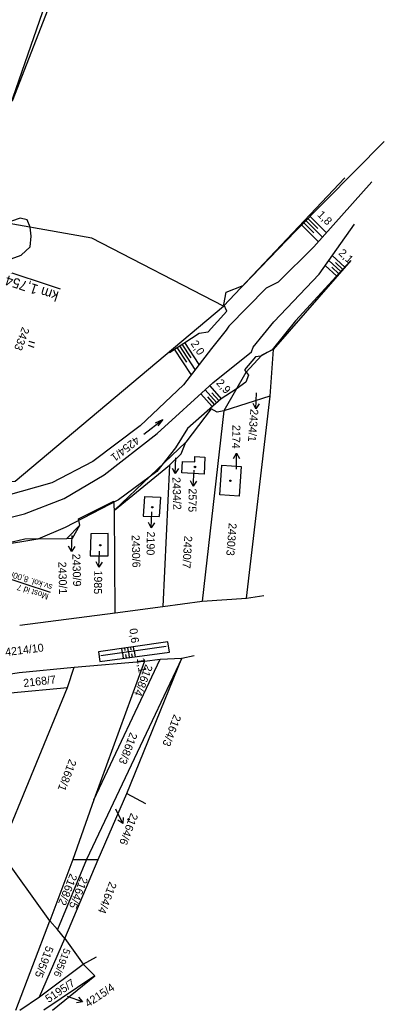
# Model space of a CAD drawing. Extents: x -659211 to -658900, y -1170600 to -1169973.
# Drawn here: x -659028.5 to -658937.4, y -1170600 to -1170352.4 of the extents above; entities that cross this region are included whole.
import ezdxf

# ---------------------------------------------------------------- set-up
doc = ezdxf.new("R2010")
doc.units = 0
for name, color, linetype in [('Vrstva 18', 7, 'Continuous'), ('Vrstva 48', 7, 'Continuous'), ('Vrstva 49', 7, 'Continuous'), ('Vrstva 53', 7, 'Continuous'), ('Vrstva 54', 7, 'Continuous'), ('Vrstva 55', 7, 'Continuous'), ('Vrstva 57', 7, 'Continuous'), ('Vrstva 58', 7, 'Continuous'), ('Vrstva 59', 7, 'Continuous'), ('Vrstva 6', 7, 'Continuous')]:
    doc.layers.add(name, color=color, linetype=linetype)

msp = doc.modelspace()

# ---------------------------------------------------------------- linework, layer by layer
at = {"layer": 'Vrstva 18'}
msp.add_line((-659079.49, -1170476.48), (-659020.95, -1170495.48), dxfattribs=at)
at = {"layer": 'Vrstva 48'}
for p, q in [((-658952.81, -1170406.77), (-658956.98, -1170402.63)), ((-658953.97, -1170404.56), (-658956.45, -1170402.1)), ((-658951.81, -1170405.65), (-658955.92, -1170401.56)), ((-658953.81, -1170407.89), (-658958.04, -1170403.69)), ((-658954.99, -1170405.66), (-658957.51, -1170403.16)), ((-658951.24, -1170412.61), (-658948.23, -1170415.37)), ((-658950.36, -1170411.38), (-658947.22, -1170414.27)), ((-658952.12, -1170413.84), (-658949.25, -1170416.47)), ((-658950.51, -1170414.3), (-658948.74, -1170415.92)), ((-658949.57, -1170413.12), (-658947.73, -1170414.82)), ((-658985.64, -1170441.12), (-658989.79, -1170434.77)), ((-658986.76, -1170438.04), (-658989.16, -1170434.36)), ((-658984.67, -1170439.86), (-658988.53, -1170433.95)), ((-658985.67, -1170436.96), (-658987.91, -1170433.54)), ((-658983.7, -1170438.6), (-658987.28, -1170433.13)), ((-658982.13, -1170444.93), (-658979.31, -1170448.12)), ((-658981.03, -1170443.92), (-658978.19, -1170447.14)), ((-658983.23, -1170445.93), (-658980.43, -1170449.11)), ((-658981.56, -1170446.7), (-658979.87, -1170448.62)), ((-658980.45, -1170445.71), (-658978.75, -1170447.63)), ((-659002.86, -1170510.67), (-659003.02, -1170509.55)), ((-659002.18, -1170510.12), (-659002.28, -1170509.45)), ((-659001.38, -1170510.46), (-659001.53, -1170509.34)), ((-659000.7, -1170509.91), (-659000.79, -1170509.24)), ((-658999.89, -1170510.25), (-659000.05, -1170509.13)), ((-659002.86, -1170510.67), (-659002.68, -1170512.05)), ((-659002.05, -1170511.12), (-659001.93, -1170511.95)), ((-659001.38, -1170510.46), (-659001.19, -1170511.85)), ((-659000.56, -1170510.91), (-659000.45, -1170511.75)), ((-658999.89, -1170510.25), (-658999.7, -1170511.65))]:
    msp.add_line(p, q, dxfattribs=at)
at = {"layer": 'Vrstva 49'}
for p, q in [((-659019.2, -1170343.88), (-659030.4, -1170372.76)), ((-658959.6, -1170405.27), (-658937.37, -1170382.87)), ((-658940.45, -1170392.95), (-658954.97, -1170409.19)), ((-659028.47, -1170402.03), (-659030.64, -1170402.78)), ((-659026.73, -1170402.47), (-659028.47, -1170402.03)), ((-659025.9, -1170404.3), (-659026.73, -1170402.47)), ((-659025.71, -1170406.53), (-659025.9, -1170404.3)), ((-658972.66, -1170418.88), (-658959.6, -1170405.27)), ((-658953.66, -1170415.98), (-658944.76, -1170403.55)), ((-659025.92, -1170409.18), (-659025.71, -1170406.53)), ((-659028.21, -1170411.25), (-659025.92, -1170409.18)), ((-658954.97, -1170409.19), (-658963.86, -1170418.03)), ((-659031.6, -1170412.49), (-659028.21, -1170411.25)), ((-658945.68, -1170412.58), (-658959.52, -1170427.66)), ((-658964.94, -1170427.92), (-658953.66, -1170415.98)), ((-658976.9, -1170420.51), (-658972.66, -1170418.88)), ((-658966.89, -1170419.54), (-658976.2, -1170429.03)), ((-658963.86, -1170418.03), (-658966.89, -1170419.54)), ((-658977.5, -1170423.58), (-658976.9, -1170420.51)), ((-658981.38, -1170430.42), (-658976.73, -1170425.24)), ((-658976.73, -1170425.24), (-658977.5, -1170423.58)), ((-658959.52, -1170427.66), (-658965.43, -1170434.93)), ((-658976.93, -1170429.99), (-658980.59, -1170434.58)), ((-658976.2, -1170429.03), (-658976.93, -1170429.99)), ((-658970.18, -1170434.3), (-658964.94, -1170427.92)), ((-658991.09, -1170435.61), (-658983.7, -1170430.79)), ((-658983.7, -1170430.79), (-658981.38, -1170430.42)), ((-658980.59, -1170434.58), (-658987.62, -1170443.68)), ((-658970.57, -1170435.41), (-658970.18, -1170434.3)), ((-658965.43, -1170434.93), (-658966.65, -1170435.61)), ((-658980.21, -1170443.18), (-658970.57, -1170435.41)), ((-658969.55, -1170436.65), (-658972.36, -1170439.95)), ((-658968.22, -1170436.51), (-658969.55, -1170436.65)), ((-658966.65, -1170435.61), (-658968.22, -1170436.51)), ((-658972.36, -1170439.95), (-658971.29, -1170441.24)), ((-658971.29, -1170441.24), (-658971.97, -1170442.97)), ((-658987.62, -1170443.68), (-658998.39, -1170453.94)), ((-658994.15, -1170455.83), (-658980.21, -1170443.18)), ((-658974.43, -1170444.79), (-658978.19, -1170447.14)), ((-658971.97, -1170442.97), (-658974.43, -1170444.79)), ((-658978.19, -1170447.14), (-658986.59, -1170454.55)), ((-658998.39, -1170453.94), (-659010.25, -1170462.82)), ((-658986.59, -1170454.55), (-658989.57, -1170459.44)), ((-659007.39, -1170466.16), (-658994.15, -1170455.83)), ((-658989.57, -1170459.44), (-658994.22, -1170465.31)), ((-659010.25, -1170462.82), (-659020.54, -1170468.18)), ((-659017.42, -1170472.09), (-659007.39, -1170466.16)), ((-658994.22, -1170465.31), (-659003.83, -1170472.45)), ((-659020.54, -1170468.18), (-659031.99, -1170471.46)), ((-659027.33, -1170475.92), (-659017.42, -1170472.09)), ((-659003.83, -1170472.45), (-659017.15, -1170479.36)), ((-659042.89, -1170479.68), (-659027.33, -1170475.92)), ((-659017.15, -1170479.36), (-659024.04, -1170482.28)), ((-659024.04, -1170482.28), (-659041.45, -1170485.07)), ((-658991.48, -1170507.92), (-659008.87, -1170510.38)), ((-658991.91, -1170509.12), (-659008.28, -1170511.44)), ((-658991.12, -1170510.48), (-658991.48, -1170507.92)), ((-659008.87, -1170510.38), (-659008.5, -1170512.84)), ((-659008.5, -1170512.84), (-658991.12, -1170510.48))]:
    msp.add_line(p, q, dxfattribs=at)
at = {"layer": 'Vrstva 53'}
msp.add_lwpolyline([(-659014.8, -1170327), (-659040.68, -1170401.69), (-659069.54, -1170465.79), (-659067.16, -1170471.54), (-659071.55, -1170492.02), (-659079.75, -1170512.52), (-659099.17, -1170514.57)], dxfattribs=at)
at = {"layer": 'Vrstva 54'}
for p, q in [((-658969.48, -1170449.67), (-658969.31, -1170445.69)), ((-658989.67, -1170465.87), (-658989.5, -1170461.89)), ((-658975.1, -1170462.05), (-658974.35, -1170460.75)), ((-658985.12, -1170468.98), (-658984.95, -1170465)), ((-658995.66, -1170479.44), (-658995.49, -1170475.46)), ((-659015.61, -1170485.35), (-659015.44, -1170481.36)), ((-659008.74, -1170489.26), (-659008.58, -1170485.27)), ((-659002.75, -1170553.31), (-659004.52, -1170549.74)), ((-659012.86, -1170597.91), (-659016.61, -1170596.56))]:
    msp.add_line(p, q, dxfattribs=at)
for points in [[(-658968.67, -1170448.41), (-658969.48, -1170449.67), (-658970.18, -1170448.36)], [(-658974.35, -1170464.75), (-658974.35, -1170460.75), (-658973.6, -1170462.05)], [(-658988.86, -1170464.61), (-658989.67, -1170465.87), (-658990.37, -1170464.56)], [(-658984.31, -1170467.73), (-658985.12, -1170468.98), (-658985.82, -1170467.68)], [(-658994.85, -1170478.18), (-658995.66, -1170479.44), (-658996.36, -1170478.13)], [(-659014.8, -1170484.09), (-659015.61, -1170485.35), (-659016.31, -1170484.04)], [(-659007.94, -1170488), (-659008.74, -1170489.26), (-659009.45, -1170487.95)], [(-659002.65, -1170551.81), (-659002.75, -1170553.31), (-659003.99, -1170552.5)], [(-659013.82, -1170596.76), (-659012.86, -1170597.91), (-659014.32, -1170598.18)]]:
    msp.add_lwpolyline(points, dxfattribs=at)
at = {"layer": 'Vrstva 55'}
for p, q in [((-658977.61, -1170423.98), (-658947.2, -1170391.89)), ((-658965.96, -1170446.49), (-658971.93, -1170496.99)), ((-658977.53, -1170450.16), (-658982.93, -1170497.74)), ((-658991.1, -1170463.73), (-658992.74, -1170499.05)), ((-658997.32, -1170471.58), (-658997.64, -1170476.49)), ((-658993.37, -1170471.75), (-658993.69, -1170476.62)), ((-659004.84, -1170475.02), (-659005, -1170472.73)), ((-659004.67, -1170500.69), (-659004.84, -1170475.02)), ((-659016.77, -1170482.05), (-659013.5, -1170478.78)), ((-659010.04, -1170547.44), (-658993.39, -1170512.29)), ((-659001.73, -1170545.81), (-658997.12, -1170548.33)), ((-659015.3, -1170562.32), (-659021.02, -1170577.69)), ((-659029.51, -1170600), (-659021.02, -1170577.69)), ((-659023.64, -1170596.66), (-659017.26, -1170582.11)), ((-659009.74, -1170591.43), (-659012.69, -1170588.49))]:
    msp.add_line(p, q, dxfattribs=at)
for points in [[(-658991.44, -1170224.37), (-659014.8, -1170327), (-659040.68, -1170401.69), (-659069.54, -1170465.79), (-659067.16, -1170471.54), (-659071.55, -1170492.02), (-659079.75, -1170512.52)], [(-659067.16, -1170471.54), (-659029.69, -1170467.77), (-658977.61, -1170423.98), (-659010.48, -1170407), (-659040.68, -1170401.69)], [(-658945.68, -1170412.58), (-658965.17, -1170434.87), (-658965.96, -1170446.49), (-658977.53, -1170450.16)], [(-658965.17, -1170434.87), (-658968.02, -1170436.23), (-658971.98, -1170440.57), (-658977.53, -1170450.16), (-658979.17, -1170450.49), (-658980.64, -1170449.67), (-658987.02, -1170458.01)], [(-658987.02, -1170458.01), (-659004.84, -1170475.02)], [(-659004.84, -1170475.02), (-658991.1, -1170463.73), (-658988.16, -1170460.96), (-658987.02, -1170458.01)], [(-658997.32, -1170471.58), (-658993.37, -1170471.75)], [(-659044.96, -1170487.72), (-659043.26, -1170487.44), (-659043.26, -1170485.64), (-659039.17, -1170485.32), (-659039.17, -1170483.84), (-659030.13, -1170482.88), (-659027.24, -1170482.21), (-659016.77, -1170482.05), (-659015.34, -1170482.04), (-659013.5, -1170478.78), (-659013.83, -1170477.14), (-659005, -1170472.73)], [(-658997.64, -1170476.49), (-658993.69, -1170476.62)], [(-659010.89, -1170486.46), (-659006.46, -1170486.44), (-659006.46, -1170480.85), (-659010.72, -1170480.9)], [(-659010.72, -1170480.9), (-659010.89, -1170486.46)], [(-659028.55, -1170503.79), (-659004.67, -1170500.69), (-658992.74, -1170499.05), (-658982.93, -1170497.74), (-658971.81, -1170496.97), (-658967.49, -1170496.3)], [(-659089.69, -1170526.68), (-659086.61, -1170526.01), (-659084.31, -1170525.55), (-659083.83, -1170525.24), (-659083.59, -1170525.57), (-659072.94, -1170523.52), (-659047.33, -1170518.48), (-659028.71, -1170515.56), (-659014.97, -1170514.26), (-658997.32, -1170512.78), (-658993.39, -1170512.29), (-658988, -1170511.97), (-658984.89, -1170511.31)], [(-658988, -1170511.97), (-659011.87, -1170562.32), (-659019.06, -1170579.82)], [(-659017.26, -1170582.11), (-659008.93, -1170562.32), (-659001.73, -1170545.81), (-658988, -1170511.97)], [(-659030.83, -1170520.63), (-659016.61, -1170519.32), (-659014.97, -1170514.26)], [(-658997.32, -1170512.78), (-659010.04, -1170547.44), (-659015.3, -1170562.32), (-659011.87, -1170562.32), (-659008.93, -1170562.32)], [(-659017.26, -1170582.11), (-659019.06, -1170579.82), (-659021.02, -1170577.69), (-659033.45, -1170560.36), (-659016.61, -1170519.32)], [(-659017.26, -1170582.11), (-659012.69, -1170588.49), (-659009.34, -1170586.64)], [(-659028.52, -1170600), (-659023.64, -1170596.66), (-659012.69, -1170588.49)], [(-659009.74, -1170591.43), (-659022.56, -1170600)], [(-659020.36, -1170600), (-659009.74, -1170591.43)]]:
    msp.add_lwpolyline(points, dxfattribs=at)
for points in [[(-658988, -1170465.7), (-658987.87, -1170462.81), (-658984.73, -1170462.92), (-658984.73, -1170461.61), (-658982.28, -1170461.77), (-658982.44, -1170466.02)], [(-658978.02, -1170463.73), (-658973.18, -1170464.09), (-658973.66, -1170471.51), (-658978.53, -1170471.19)]]:
    msp.add_lwpolyline(points, close=True, dxfattribs=at)
at = {"layer": 'Vrstva 57'}
msp.add_circle((-659001.33, -1170552.29), 0.175, dxfattribs=at)
at = {"layer": 'Vrstva 58'}
for p, q in [((-659024.74, -1170433.28), (-659026.17, -1170432.82)), ((-659026.48, -1170433.77), (-659025.05, -1170434.23)), ((-658997.47, -1170456.01), (-658992.72, -1170452.34))]:
    msp.add_line(p, q, dxfattribs=at)
msp.add_lwpolyline([(-658994.61, -1170453.16), (-658992.72, -1170452.34), (-658994, -1170453.96)], dxfattribs=at)
at = {"layer": 'Vrstva 59'}
for centre in [(-658984.71, -1170464.21), (-658975.85, -1170467.64), (-658995.41, -1170474.26), (-659008.42, -1170483.76)]:
    msp.add_circle(centre, 0.175, dxfattribs=at)
at = {"layer": 'Vrstva 6'}
msp.add_line((-659054.34, -1170407.94), (-659018.47, -1170419.64), dxfattribs=at)

# ---------------------------------------------------------------- texts
at = {"layer": 'Vrstva 18'}
for s, p in [('sv.kol. 8,00m, vol.v. 3,85m', (-659020.24, -1170493.65)), ('Most id 7', (-659021.18, -1170496))]:
    msp.add_text(s, height=1.5, rotation=162.0228, dxfattribs=at).set_placement(p)
at = {"layer": 'Vrstva 48'}
for s, rotation, p in [('1,8', 315.2166, (-658954.25, -1170401.32)), ('2,1', 317.45, (-658948.96, -1170410.95)), ('2,0', 303.1534, (-658985.87, -1170433.36)), ('2,9', 311.416, (-658979.52, -1170443.3)), ('0,6', 278.0511, (-659001.14, -1170504.68)), ('1,1', 277.745, (-658999.28, -1170512.05))]:
    msp.add_text(s, height=2, rotation=rotation, dxfattribs=at).set_placement(p)
at = {"layer": 'Vrstva 57'}
for s, height, rotation, p in [('2433', 2, 249.6006, (-659027.91, -1170429.07)), ('2434/1', 2, 265.553, (-658970.82, -1170449.67)), ('2174', 2, 268.9602, (-658975.33, -1170453.68)), ('4254/1', 2, 217.5784, (-658999.5, -1170456.42)), ('2434/2', 2, 271.6254, (-658990.35, -1170466.76)), ('2575', 2, 268.9602, (-658986.26, -1170469.55)), ('2430/3', 2, 265.553, (-658976.24, -1170478.16)), ('2430/6', 2, 271.6254, (-659000.57, -1170481.21)), ('2190', 2, 268.9602, (-658996.72, -1170480.32)), ('2430/7', 2, 266.583, (-658987.36, -1170481.38)), ('2430/9', 2, 271.6254, (-659015.41, -1170485.92)), ('2430/1', 2, 271.6254, (-659018.92, -1170487.91)), ('1985', 2, 268.9602, (-659009.89, -1170490.06)), ('4214/10', 2, 6.9779, (-659032.06, -1170511.48)), ('2168/4', 2, 248.8639, (-658997.06, -1170513.39)), ('2168/7', 2, 6.6475, (-659027.53, -1170519.23)), ('2164/3', 2, 248.8639, (-658989.95, -1170525.92)), ('2168/3', 2, 248.8639, (-659000.89, -1170530.39)), ('2168/1', 2, 248.8639, (-659016.13, -1170537.09)), ('2164/6', 2, 248.8639, (-659000.73, -1170550.58)), ('2168/2', 2, 248.0897, (-659015.93, -1170565.7)), ('2164/5', 2, 248.2479, (-659013.25, -1170566.49)), ('2164/4', 2, 248.8639, (-659006.08, -1170567.74)), ('5195/5', 2, 248.8639, (-659021.88, -1170583.77)), ('5195/6', 1.8, 248.8639, (-659017.46, -1170584.38)), ('5195/7', 2, 33.6464, (-659021.33, -1170598.23)), ('4215/4', 2, 33.6464, (-659011.43, -1170599.35))]:
    msp.add_text(s, height=height, rotation=rotation, dxfattribs=at).set_placement(p)
at = {"layer": 'Vrstva 6'}
msp.add_text('km 1,754', height=2.5, rotation=161.9415, dxfattribs=at).set_placement((-659018.61, -1170420.49))

doc.saveas('drawing.dxf')
